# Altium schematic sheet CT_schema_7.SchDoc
size 421 x 246 mm
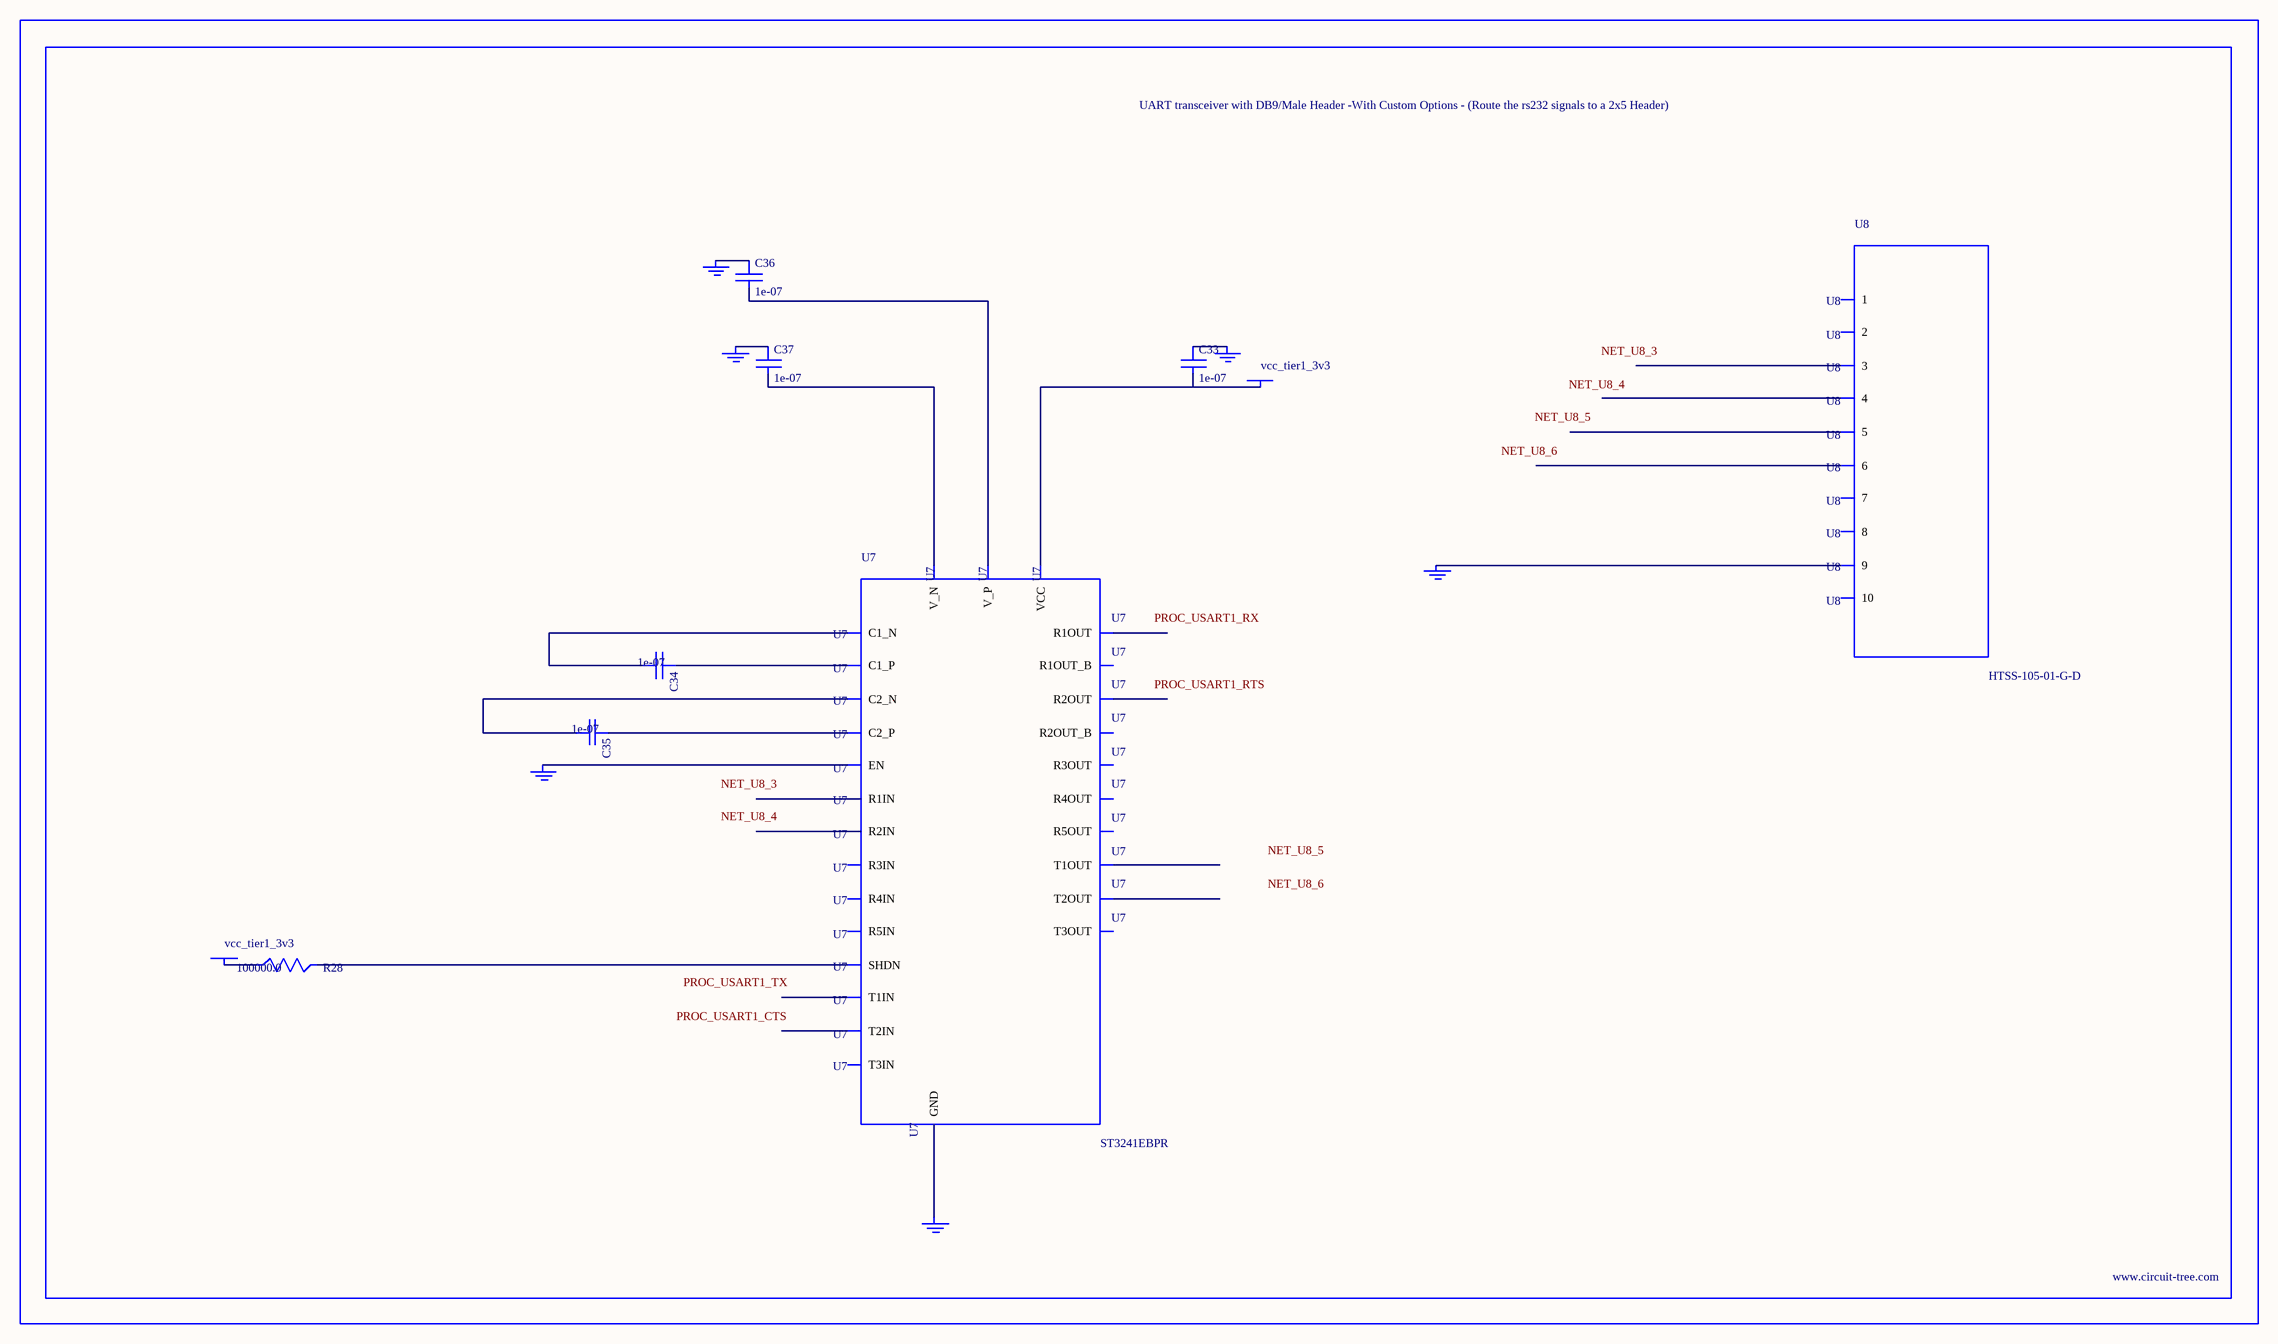
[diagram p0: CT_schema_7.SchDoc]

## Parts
BORDER6  (no value)
C33  1e-07  [C0402]
C34  1e-07  [C0402]
C35  1e-07  [C0402]
C36  1e-07  [C0402]
C37  1e-07  [C0402]
GND_INSTANCE_6_0  (no value)
GND_INSTANCE_6_1  (no value)
GND_INSTANCE_6_2  (no value)
GND_INSTANCE_6_3  (no value)
GND_INSTANCE_6_4  (no value)
GND_INSTANCE_6_5  (no value)
POWER_INSTANCE_6_0  vcc_tier1_3v3
POWER_INSTANCE_6_1  vcc_tier1_3v3
R28  100000.0  [R0603]
U7  ST3241EBPR  [SSOP-28]
U8  HTSS-105-01-G-D  [HTSS-105-01-G-D]

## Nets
NetC33_1: C33.1 GND_INSTANCE_6_2.0(GND)
NetC33_2: C33.2 POWER_INSTANCE_6_1.0(PWR) U7.26(VCC)
NetC34_1: C34.1 U7.28(C1_P)
NetC34_2: C34.2 U7.24(C1_N)
NetC35_1: C35.1 U7.1(C2_P)
NetC35_2: C35.2 U7.2(C2_N)
NetC36_1: C36.1 GND_INSTANCE_6_3.0(GND)
NetC36_2: C36.2 U7.27(V_P)
NetC37_1: C37.1 GND_INSTANCE_6_0.0(GND)
NetC37_2: C37.2 U7.3(V_N)
NetGND_INSTANCE_6_1_0: GND_INSTANCE_6_1.0(GND) U7.23(EN)
NetGND_INSTANCE_6_4_0: GND_INSTANCE_6_4.0(GND) U7.25(GND)
NetGND_INSTANCE_6_5_0: GND_INSTANCE_6_5.0(GND) U8.9
NetPOWER_INSTANCE_6_0_0: POWER_INSTANCE_6_0.0(PWR) R28.1
NetR28_2: R28.2 U7.22(SHDN)

Not connected (* = marked no-connect by the designer): U7 4(R1IN) 5(R2IN) 6(R3IN) 7(R4IN) 8(R5IN) 9(T1OUT) 10(T2OUT) 11(T3OUT) 12(T3IN) 13(T2IN) 14(T1IN) 15(R5OUT) 16(R4OUT) 17(R3OUT) 18(R2OUT) 19(R1OUT) 20(R2OUT_B) 21(R1OUT_B); U8 1 2 3 4 5 6 7 8 10

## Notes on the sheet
- Labels drawn without touching a wire or pin: NET_U8_3, NET_U8_4, NET_U8_5, NET_U8_6, PROC_USART1_CTS, PROC_USART1_RTS, PROC_USART1_RX, PROC_USART1_TX

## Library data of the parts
BORDER6 = BORDER_PAGE6
C33-C37 = C0402C104K3RACTU
GND_INSTANCE_6_0-GND_INSTANCE_6_5 = GND
POWER_INSTANCE_6_0 POWER_INSTANCE_6_1 = PWR
R28 = RC0603JR-07100KL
